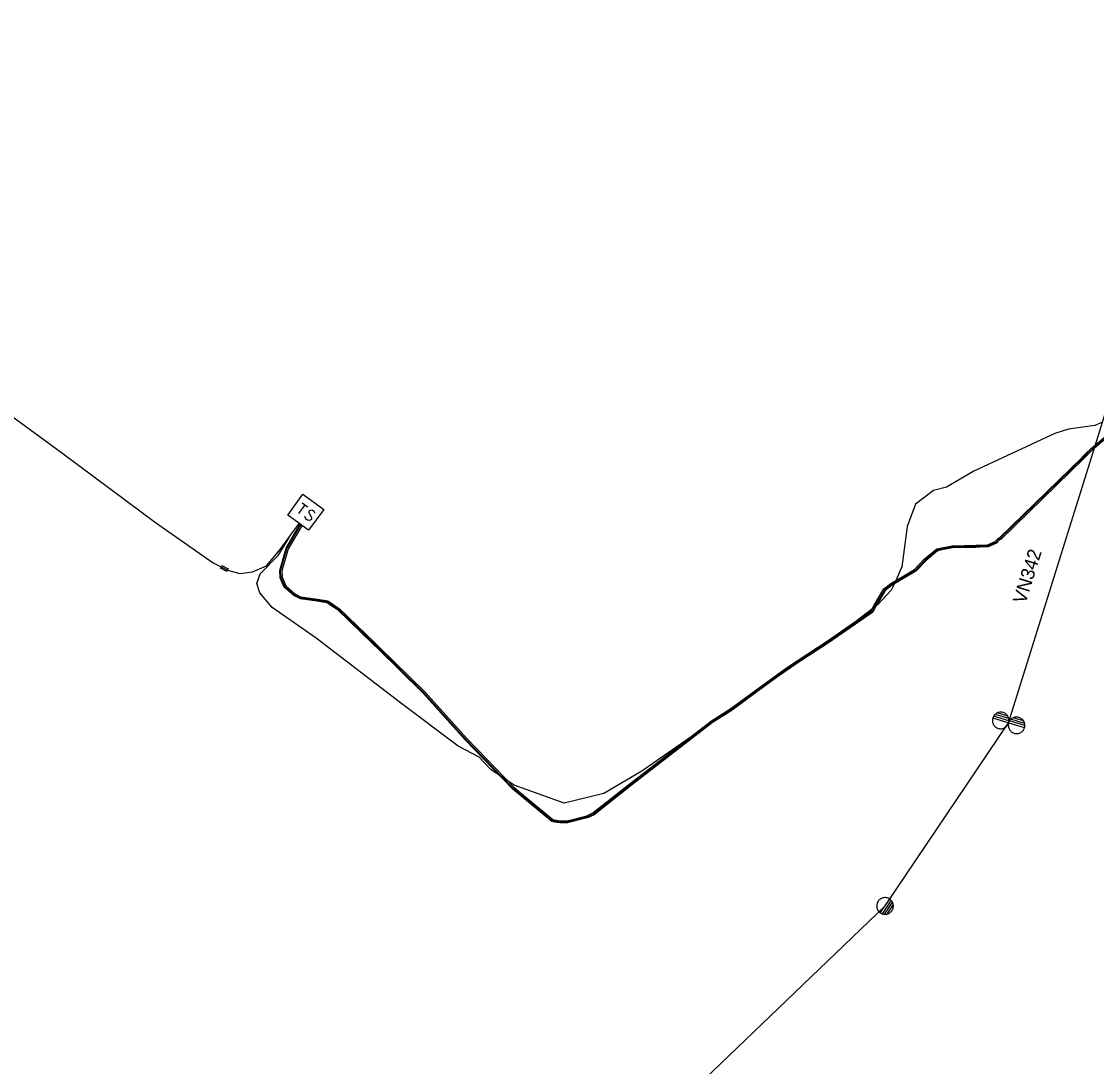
# Model space of a CAD drawing. Extents: x -643811 to -636362, y -1117362 to -1108614.
# Drawn here: x -641107.8 to -640949.8, y -1116043.8 to -1115890.2 of the extents above; entities that cross this region are included whole.
import ezdxf

# ---------------------------------------------------------------- set-up
doc = ezdxf.new("R2010")
doc.units = 0
for name, color, linetype in [('1', 7, 'Continuous'), ('13', 7, 'Continuous'), ('20', 7, 'Continuous'), ('25', 7, 'Continuous'), ('3', 7, 'Continuous'), ('5', 7, 'Continuous'), ('9', 7, 'Continuous')]:
    doc.layers.add(name, color=color, linetype=linetype)

# ---------------------------------------------------------------- blocks, each defined once
blk = doc.blocks.new('VN450')
at = {"layer": '13'}
for points in [[(0, 0), (-0.01, 0.13), (-0.03, 0.25), (-0.06, 0.38), (-0.11, 0.5), (-0.16, 0.61), (-0.23, 0.72), (-0.31, 0.82), (-0.4, 0.91), (-0.5, 0.99), (-0.61, 1.06), (-0.72, 1.11), (-0.84, 1.16), (-0.97, 1.19), (-1.09, 1.21), (-1.22, 1.22), (-1.35, 1.21), (-1.47, 1.19), (-1.59, 1.16), (-1.71, 1.11), (-1.83, 1.06), (-1.93, 0.99), (-2.03, 0.91), (-2.12, 0.82), (-2.2, 0.72), (-2.27, 0.61), (-2.33, 0.5), (-2.38, 0.38), (-2.41, 0.25), (-2.43, 0.13), (-2.44, 0), (-2.43, -0.13), (-2.41, -0.25), (-2.38, -0.38), (-2.33, -0.5), (-2.27, -0.61), (-2.2, -0.72), (-2.12, -0.82), (-2.03, -0.91), (-1.93, -0.99), (-1.83, -1.06), (-1.71, -1.11), (-1.59, -1.16), (-1.47, -1.19), (-1.35, -1.21), (-1.22, -1.22), (-1.09, -1.21), (-0.97, -1.19), (-0.84, -1.16), (-0.72, -1.11), (-0.61, -1.06), (-0.5, -0.99), (-0.4, -0.91), (-0.31, -0.82), (-0.23, -0.72), (-0.16, -0.61), (-0.11, -0.5), (-0.06, -0.38), (-0.03, -0.25), (-0.01, -0.13), (0, 0)], [(-2.44, 0), (2.44, 0)], [(2.44, 0), (2.43, 0.13), (2.41, 0.25), (2.38, 0.38), (2.33, 0.5), (2.27, 0.61), (2.2, 0.72), (2.12, 0.82), (2.03, 0.91), (1.94, 0.99), (1.83, 1.06), (1.71, 1.11), (1.6, 1.16), (1.47, 1.19), (1.35, 1.21), (1.22, 1.22), (1.09, 1.21), (0.97, 1.19), (0.84, 1.16), (0.72, 1.11), (0.61, 1.06), (0.5, 0.99), (0.4, 0.91), (0.31, 0.82), (0.23, 0.72), (0.16, 0.61), (0.11, 0.5), (0.06, 0.38), (0.03, 0.25), (0.01, 0.13), (0, 0), (0.01, -0.13), (0.03, -0.25), (0.06, -0.38), (0.11, -0.5), (0.16, -0.61), (0.23, -0.72), (0.31, -0.82), (0.4, -0.91), (0.5, -0.99), (0.61, -1.06), (0.72, -1.11), (0.84, -1.16), (0.97, -1.19), (1.09, -1.21), (1.22, -1.22), (1.35, -1.21), (1.47, -1.19), (1.6, -1.16), (1.71, -1.11), (1.83, -1.06), (1.94, -0.99), (2.03, -0.91), (2.12, -0.82), (2.2, -0.72), (2.27, -0.61), (2.33, -0.5), (2.38, -0.38), (2.41, -0.25), (2.43, -0.13), (2.44, 0)], [(-2.4, -0.31), (-0.04, -0.31)], [(-2.26, -0.61), (-0.17, -0.61)], [(-2.01, -0.92), (-0.42, -0.92)], [(0.04, -0.31), (2.4, -0.31)], [(0.17, -0.61), (2.27, -0.61)], [(0.42, -0.92), (2.02, -0.92)]]:
    blk.add_lwpolyline(points, dxfattribs=at)
blk = doc.blocks.new('VN440')
at = {"layer": '13'}
for points in [[(1.22, 0), (1.21, 0.13), (1.19, 0.25), (1.16, 0.38), (1.11, 0.5), (1.05, 0.61), (0.98, 0.72), (0.9, 0.82), (0.81, 0.91), (0.71, 0.99), (0.6, 1.06), (0.49, 1.12), (0.37, 1.16), (0.25, 1.2), (0.12, 1.22), (-0.01, 1.22), (-0.14, 1.22), (-0.26, 1.2), (-0.39, 1.16), (-0.51, 1.12), (-0.62, 1.06), (-0.73, 0.99), (-0.83, 0.91), (-0.92, 0.82), (-1, 0.72), (-1.07, 0.61), (-1.13, 0.5), (-1.18, 0.38), (-1.21, 0.25), (-1.23, 0.13), (-1.24, 0), (-1.23, -0.13), (-1.21, -0.26), (-1.18, -0.38), (-1.13, -0.5), (-1.07, -0.62), (-1, -0.73), (-0.92, -0.83), (-0.83, -0.92), (-0.73, -1), (-0.62, -1.07), (-0.51, -1.13), (-0.39, -1.17), (-0.26, -1.2), (-0.14, -1.23), (-0.01, -1.23), (0.12, -1.23), (0.25, -1.2), (0.37, -1.17), (0.49, -1.13), (0.6, -1.07), (0.71, -1), (0.81, -0.92), (0.9, -0.83), (0.98, -0.73), (1.05, -0.62), (1.11, -0.5), (1.16, -0.38), (1.19, -0.26), (1.21, -0.13), (1.22, 0)], [(-1.24, 0), (1.22, 0)], [(-1.18, -0.34), (1.1, -0.34)], [(-1.01, -0.63), (0.97, -0.63)], [(-0.74, -0.92), (0.68, -0.92)]]:
    blk.add_lwpolyline(points, dxfattribs=at)
blk = doc.blocks.new('VN640')
at = {"layer": '25'}
for points in [[(-1.89, 1.89), (1.89, 1.89)], [(-1.89, -1.89), (-1.89, 1.89)], [(1.89, 1.89), (1.89, -1.89)], [(-1.26, 0.79), (-0.22, 0.79)], [(-0.73, 0.79), (-0.73, -0.79)], [(1.2, 0.66), (0.94, 0.79), (0.66, 0.79), (0.41, 0.66), (0.28, 0.47), (0.28, 0.41), (0.41, 0.22), (1.13, -0.16), (1.26, -0.32), (1.26, -0.47), (1.13, -0.66), (0.91, -0.79), (0.63, -0.79), (0.5, -0.73), (0.28, -0.6)], [(1.89, -1.89), (-1.89, -1.89)]]:
    blk.add_lwpolyline(points, dxfattribs=at)

msp = doc.modelspace()

# ---------------------------------------------------------------- linework, layer by layer
at = {"layer": '1'}
for points in [[(-640962.72, -1115993.27), (-640950.02, -1115952.58), (-640948.93, -1115949.09), (-640944.87, -1115936.09)], [(-641036.66, -1116132.45), (-641021.94, -1116059.6), (-640980.88, -1116020.16), (-640962.72, -1115993.27)]]:
    msp.add_lwpolyline(points, dxfattribs=at)
at = {"layer": '20'}
msp.add_lwpolyline([(-640945.25, -1115948.85), (-640950.4, -1115953.17), (-640951.65, -1115954.41), (-640951.79, -1115954.27), (-640951.79, -1115954.27), (-640951.79, -1115954.27), (-640951.86, -1115954.2), (-640951.86, -1115954.2), (-640951.37, -1115953.7), (-640950.61, -1115952.95), (-640945.45, -1115948.62)], dxfattribs=at)
for points in [[(-640951.86, -1115954.2), (-640951.79, -1115954.27), (-640951.79, -1115954.27), (-640951.79, -1115954.27), (-640951.65, -1115954.41), (-640963.87, -1115966.33), (-640963.89, -1115966.34), (-640963.96, -1115966.27), (-640964.03, -1115966.2), (-640964.03, -1115966.2), (-640964.03, -1115966.2), (-640964.1, -1115966.13), (-640951.88, -1115954.22), (-640951.86, -1115954.2)], [(-641069.66, -1115971.91), (-641069.76, -1115971.91), (-641069.79, -1115970.88), (-641068.86, -1115967.59), (-641066.8, -1115964.05), (-641066.54, -1115964.2), (-641068.58, -1115967.71), (-641069.49, -1115970.91), (-641069.46, -1115971.87), (-641069.46, -1115971.9)], [(-641027.58, -1116007.67), (-641024.72, -1116006.93), (-641023.8, -1116006.5), (-641018.31, -1116002.16), (-641006.38, -1115992.96), (-641003.52, -1115991.16), (-640999.88, -1115988.46), (-640995.22, -1115985.09), (-640989.38, -1115981.25), (-640982.91, -1115976.78), (-640982.5, -1115975.96), (-640981.07, -1115973.6), (-640980.02, -1115972.77), (-640976.54, -1115970.72), (-640975.11, -1115969.23), (-640973.25, -1115967.7), (-640971.02, -1115967.24), (-640967.56, -1115967.18), (-640965.81, -1115967.1), (-640964.69, -1115966.62), (-640964.18, -1115966.06), (-640964.03, -1115966.2), (-640964.03, -1115966.2), (-640964.03, -1115966.2), (-640963.96, -1115966.27), (-640963.96, -1115966.27), (-640964.51, -1115966.87), (-640965.74, -1115967.4), (-640966.3, -1115967.42), (-640967.55, -1115967.48), (-640968.54, -1115967.5), (-640970.99, -1115967.54), (-640972.51, -1115967.86), (-640973.12, -1115967.98), (-640973.4, -1115968.21), (-640974.9, -1115969.45), (-640976.36, -1115970.96), (-640979.85, -1115973.02), (-640980.84, -1115973.8), (-640982.23, -1115976.11), (-640982.67, -1115976.99), (-640989.21, -1115981.5), (-640995.05, -1115985.33), (-640999.7, -1115988.7), (-641003.35, -1115991.41), (-641004.4, -1115992.07), (-641006.21, -1115993.2), (-641018.13, -1116002.4), (-641019.81, -1116003.73), (-641023.64, -1116006.76), (-641024.62, -1116007.21), (-641025.02, -1116007.32), (-641027.53, -1116007.97), (-641027.55, -1116007.87), (-641027.6, -1116007.68)], [(-641078.33, -1115970.16), (-641077.4, -1115970.65), (-641077.58, -1115971.01), (-641078.51, -1115970.52)], [(-641069.48, -1115971.83), (-641069.46, -1115971.87), (-641068.92, -1115973.13), (-641067.59, -1115974.3), (-641066.76, -1115974.74), (-641066.73, -1115974.75), (-641066.82, -1115974.93), (-641066.85, -1115974.99), (-641066.87, -1115975.02), (-641067.34, -1115974.77), (-641067.76, -1115974.55), (-641069.17, -1115973.31), (-641069.75, -1115971.95), (-641069.66, -1115971.91)], [(-641066.79, -1115974.73), (-641066.76, -1115974.74), (-641064.29, -1115975.1), (-641062.75, -1115975.36), (-641061.03, -1115976.49), (-641055.93, -1115981.43), (-641055.73, -1115981.62), (-641055.87, -1115981.76), (-641055.89, -1115981.78), (-641055.94, -1115981.83), (-641055.94, -1115981.83), (-641056.12, -1115981.66), (-641061.22, -1115976.73), (-641062.32, -1115976), (-641062.86, -1115975.65), (-641063.47, -1115975.54), (-641064.34, -1115975.4), (-641066.83, -1115975.03), (-641066.83, -1115975), (-641066.82, -1115974.93)], [(-641055.73, -1115981.62), (-641055.21, -1115982.13), (-641048.52, -1115988.7), (-641042.3, -1115995.6), (-641035.37, -1116002.78), (-641029.69, -1116007.49), (-641028.62, -1116007.67), (-641027.58, -1116007.67), (-641027.55, -1116007.67), (-641027.55, -1116007.87), (-641027.55, -1116007.97), (-641028.65, -1116007.97), (-641029.44, -1116007.84), (-641029.82, -1116007.77), (-641035.58, -1116003), (-641042.52, -1115995.81), (-641048.73, -1115988.91), (-641055.41, -1115982.36), (-641055.94, -1115981.83), (-641055.94, -1115981.83), (-641055.89, -1115981.78), (-641055.87, -1115981.76)]]:
    msp.add_lwpolyline(points, close=True, dxfattribs=at)
at = {"layer": '5'}
for points in [[(-641186.49, -1115890.22), (-641186.13, -1115890.89), (-641182.66, -1115893.58), (-641181.09, -1115894.77), (-641170.38, -1115902.66), (-641161, -1115909.31), (-641144.63, -1115921.99), (-641128.71, -1115933.77), (-641115.47, -1115943.66), (-641101.69, -1115953.7), (-641088.06, -1115963.85), (-641079.58, -1115969.74), (-641078.42, -1115970.34), (-641077.49, -1115970.83), (-641075.7, -1115971.3), (-641073.8, -1115971.1), (-641071.77, -1115970.22), (-641069.76, -1115967.82), (-641067.78, -1115965.11), (-641066.92, -1115963.94)], [(-640945.38, -1115948.7), (-640950.02, -1115952.58), (-640950.54, -1115953.02), (-640951.79, -1115954.27), (-640964.03, -1115966.2), (-640964.57, -1115966.79), (-640965.76, -1115967.3), (-640967.55, -1115967.38), (-640971, -1115967.44), (-640973.16, -1115967.89), (-640974.97, -1115969.38), (-640976.42, -1115970.88), (-640979.46, -1115972.68), (-640979.91, -1115972.94), (-640980.92, -1115973.73), (-640982.32, -1115976.06), (-640982.42, -1115976.26), (-640982.75, -1115976.92), (-640989.27, -1115981.42), (-640990.67, -1115982.34), (-640995.11, -1115985.25), (-640999.76, -1115988.62), (-641000.76, -1115989.36), (-641003.41, -1115991.33), (-641005.31, -1115992.52), (-641006.27, -1115993.12), (-641007.1, -1115993.76), (-641018.19, -1116002.32), (-641023.69, -1116006.67), (-641024.65, -1116007.12), (-641027.55, -1116007.87), (-641028.64, -1116007.87), (-641029.78, -1116007.68), (-641035.51, -1116002.93), (-641037.14, -1116001.24), (-641042.45, -1115995.74), (-641048.66, -1115988.84), (-641055.87, -1115981.76), (-641061.16, -1115976.65), (-641062.82, -1115975.55), (-641064.32, -1115975.3), (-641066.82, -1115974.93), (-641067.7, -1115974.47), (-641069.09, -1115973.25), (-641069.66, -1115971.91), (-641069.69, -1115970.89), (-641068.77, -1115967.63), (-641066.71, -1115964.1)]]:
    msp.add_lwpolyline(points, dxfattribs=at)
at = {"layer": '9'}
msp.add_lwpolyline([(-640948.93, -1115949.09), (-640950.03, -1115949.6), (-640953.93, -1115950.13), (-640955.93, -1115950.74), (-640967.81, -1115956.27), (-640971.87, -1115958.62), (-640973.77, -1115959.12), (-640976.4, -1115961.12), (-640977.64, -1115964.42), (-640978.42, -1115970.36), (-640979.46, -1115972.68), (-640979.96, -1115973.77), (-640981.96, -1115975.9), (-640982.42, -1115976.26), (-640987.14, -1115979.88), (-640990.67, -1115982.34), (-640999.36, -1115988.39), (-641000.76, -1115989.36), (-641005.31, -1115992.52), (-641007.1, -1115993.76), (-641016.63, -1116000.37), (-641022.2, -1116003.63), (-641028.02, -1116005.08), (-641035.38, -1116002.4), (-641037.14, -1116001.24), (-641038.82, -1116000.13), (-641040.54, -1115998.32), (-641043.61, -1115996.68), (-641052.06, -1115990.31), (-641064.48, -1115980.83), (-641070.93, -1115976.3), (-641072.74, -1115974.17), (-641073.21, -1115972.77), (-641072.69, -1115971.35), (-641070.07, -1115968.66), (-641068.65, -1115966.37), (-641068.43, -1115966.01)], dxfattribs=at)

# ---------------------------------------------------------------- block references
at = {"layer": '13'}
for name, p, rotation in [('VN450', (-640962.72, -1115993.27), 163), ('VN440', (-640980.88, -1116020.16), 56)]:
    msp.add_blockref(name, p, dxfattribs=dict(at, rotation=rotation))
at = {"layer": '25', "rotation": -36.000000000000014}
msp.add_blockref('VN640', (-641065.99, -1115962.32), dxfattribs=at)

# ---------------------------------------------------------------- texts
at = {"layer": '3'}
msp.add_text('VN342', height=1.989, rotation=72.6487, dxfattribs=at).set_placement((-640960.26, -1115975.89))

doc.saveas('drawing.dxf')
